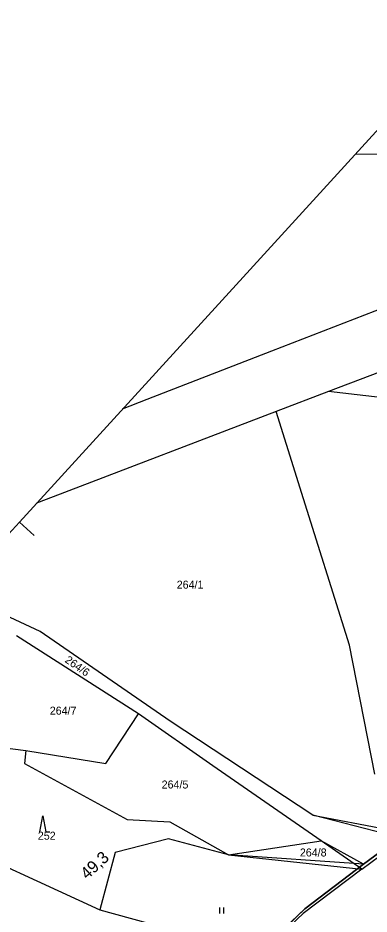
# Model space of a CAD drawing. Extents: x -678683 to -677755, y -1006946 to -1005971.
# Drawn here: x -678399.9 to -678311.9, y -1006533.9 to -1006309.9 of the extents above; entities that cross this region are included whole.
import ezdxf

# ---------------------------------------------------------------- set-up
doc = ezdxf.new("R2010")
doc.units = 0
for name, color, linetype in [('I_2_4_předběžný_vykres - SŽDC', 7, 'Continuous'), ('kilometráž - Vrstva 7', 7, 'Continuous'), ('MapaKN - Mladejov+Strelec_dosavani+nova_situace - Vrstva 1', 7, 'Continuous'), ('MapaKN - Mladejov+Strelec_dosavani+nova_situace - Vrstva 11', 7, 'Continuous'), ('MapaKN - Mladejov+Strelec_dosavani+nova_situace - Vrstva 18', 7, 'Continuous'), ('MapaKN - Mladejov+Strelec_dosavani+nova_situace - Vrstva 25', 7, 'Continuous'), ('MapaKN - původní vrstava 1', 7, 'Continuous'), ('ramy - Sekce lichá', 7, 'Continuous')]:
    doc.layers.add(name, color=color, linetype=linetype)

msp = doc.modelspace()

# ---------------------------------------------------------------- linework, layer by layer
at = {"layer": 'I_2_4_předběžný_vykres - SŽDC'}
for p, q in [((-678308.95, -1006518.13), (-678313.38, -1006521.44)), ((-678313.38, -1006521.44), (-678328.04, -1006532.61)), ((-678328.04, -1006532.61), (-678346.7, -1006550.29))]:
    msp.add_line(p, q, dxfattribs=at)
at = {"layer": 'MapaKN - Mladejov+Strelec_dosavani+nova_situace - Vrstva 1'}
for points in [[(-678315.33, -1006343.88), (-678279.85, -1006344.02)], [(-678294.96, -1006377.2), (-678336.38, -1006393.2)], [(-678267.26, -1006382.54), (-678322.15, -1006403.3)], [(-678336.38, -1006393.2), (-678367.58, -1006405.25)], [(-678322.15, -1006403.3), (-678335.2, -1006408.25)], [(-678246.7, -1006412.02), (-678322.15, -1006403.3)], [(-678367.58, -1006405.25), (-678373.73, -1006407.72)], [(-678335.2, -1006408.25), (-678391.05, -1006429.56)], [(-678330.02, -1006424.75), (-678335.2, -1006408.25)], [(-678329.27, -1006427.15), (-678330.02, -1006424.75)], [(-678316.86, -1006466.7), (-678329.27, -1006427.15)], [(-678391.05, -1006429.56), (-678395.22, -1006431.22)], [(-678394.3, -1006463.24), (-678410.82, -1006455.57)], [(-678369.7, -1006483.86), (-678400.24, -1006464.34)], [(-678361.78, -1006485.71), (-678394.3, -1006463.24)], [(-678310.51, -1006498.93), (-678316.86, -1006466.7)], [(-678377.85, -1006496.26), (-678369.7, -1006483.86)], [(-678351.03, -1006496.84), (-678369.7, -1006483.86)], [(-678326.05, -1006509.2), (-678361.78, -1006485.71)], [(-678403.74, -1006492.28), (-678397.88, -1006493.04)], [(-678397.88, -1006493.04), (-678398.21, -1006496.27)], [(-678397.88, -1006493.04), (-678377.85, -1006496.26)], [(-678398.21, -1006496.27), (-678372.49, -1006510.28)], [(-678323.91, -1006515.59), (-678351.03, -1006496.84)], [(-678372.49, -1006510.28), (-678361.83, -1006510.84)], [(-678361.83, -1006510.84), (-678347.12, -1006519.11)], [(-678420.43, -1006513.99), (-678379.35, -1006532.79)], [(-678362.17, -1006515.05), (-678375.48, -1006518.51)], [(-678347.12, -1006519.11), (-678362.17, -1006515.05)], [(-678347.12, -1006519.11), (-678323.91, -1006515.59)], [(-678375.48, -1006518.51), (-678379.35, -1006532.79)], [(-678379.35, -1006532.79), (-678367.5, -1006536.07)]]:
    msp.add_lwpolyline(points, dxfattribs=at)
at = {"layer": 'MapaKN - Mladejov+Strelec_dosavani+nova_situace - Vrstva 11'}
for points in [[(-678326.05, -1006509.2), (-678307.61, -1006512.66)], [(-678313.38, -1006521.44), (-678323.91, -1006515.59)], [(-678313.38, -1006521.44), (-678308.95, -1006518.13)], [(-678313.38, -1006521.44), (-678347.12, -1006519.11)], [(-678328.04, -1006532.61), (-678313.38, -1006521.44)], [(-678346.7, -1006550.29), (-678328.04, -1006532.61)]]:
    msp.add_lwpolyline(points, dxfattribs=at)
at = {"layer": 'MapaKN - Mladejov+Strelec_dosavani+nova_situace - Vrstva 25'}
for points in [[(-678394.4, -1006513.35), (-678393.65, -1006509.35), (-678392.9, -1006513.35), (-678391.9, -1006513.35)], [(-678349.32, -1006533.77), (-678349.32, -1006532.27)], [(-678348.28, -1006533.77), (-678348.28, -1006532.27)]]:
    msp.add_lwpolyline(points, dxfattribs=at)
at = {"layer": 'MapaKN - původní vrstava 1'}
for points in [[(-678307.93, -1006513.86), (-678326.05, -1006509.2)], [(-678313.73, -1006522.63), (-678323.91, -1006515.59)], [(-678347.12, -1006519.11), (-678313.73, -1006522.63)], [(-678313.73, -1006522.63), (-678309.29, -1006519.33)], [(-678313.73, -1006522.63), (-678328.43, -1006533.75)], [(-678328.43, -1006533.75), (-678347.15, -1006551.37)]]:
    msp.add_lwpolyline(points, dxfattribs=at)
at = {"layer": 'ramy - Sekce lichá'}
for p, q in [((-678399.5, -1006435.89), (-678257.76, -1006280.94)), ((-678541.24, -1006590.84), (-678399.5, -1006435.89)), ((-678399.5, -1006435.89), (-678395.81, -1006439.27))]:
    msp.add_line(p, q, dxfattribs=at)

# ---------------------------------------------------------------- texts
at = {"layer": 'kilometráž - Vrstva 7'}
msp.add_text('49,3', height=3, rotation=42.7281, dxfattribs=at).set_placement((-678382.53, -1006525.41))
at = {"layer": 'MapaKN - Mladejov+Strelec_dosavani+nova_situace - Vrstva 18'}
for s, p in [('264/1', (-678360.11, -1006452.55)), ('264/7', (-678391.89, -1006484.04)), ('264/5', (-678363.88, -1006502.5)), ('252', (-678394.88, -1006515.3)), ('264/8', (-678329.28, -1006519.49))]:
    msp.add_text(s, height=2, dxfattribs=at).set_placement(p)
msp.add_text('264/6', height=2, rotation=325.0026, dxfattribs=at).set_placement((-678388.28, -1006470.78))

doc.saveas('drawing.dxf')
